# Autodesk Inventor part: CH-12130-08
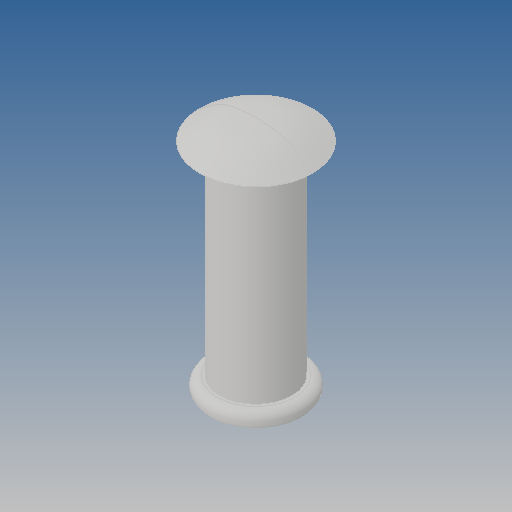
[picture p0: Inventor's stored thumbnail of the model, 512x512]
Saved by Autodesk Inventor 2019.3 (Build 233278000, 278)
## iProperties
Created: 2017-11
Part Number: CH-12130-08
Material: Ogólny
Document SubType Name: Modeling
Designer: Admin
Density: 1 g/cm^3
Appearance: Domyślna
Author: Admin
Revision Number: ÈÎºÎ
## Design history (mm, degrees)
feature "Ô²½Ç2"
node "Bryła1"
